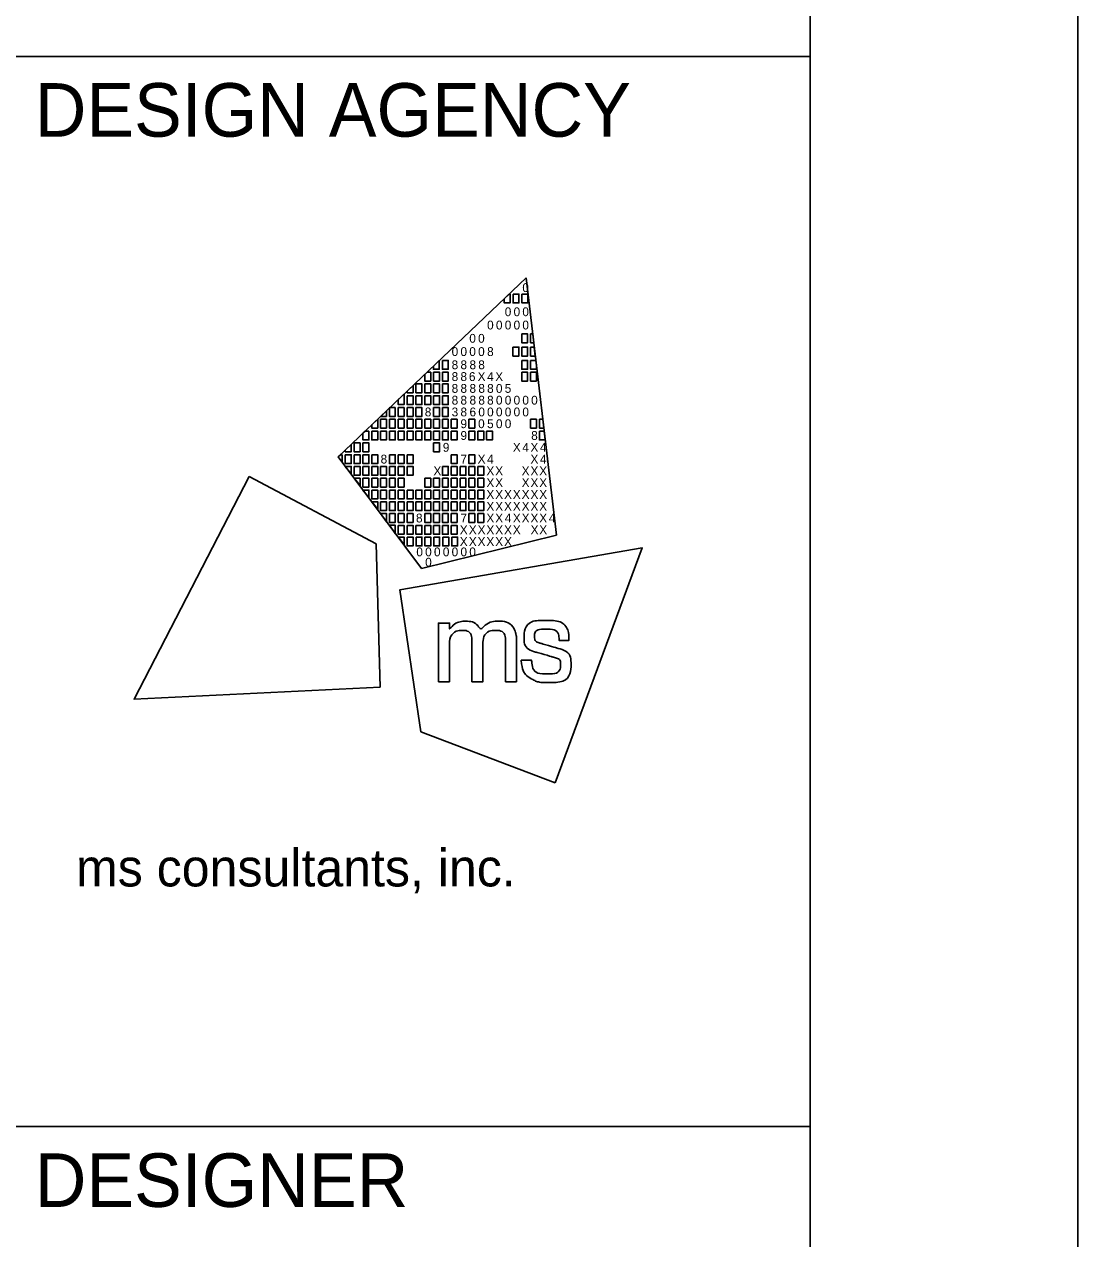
# Model space of a CAD drawing. Extents: x 0.1 to 34.1, y 0.1 to 22.1.
# Drawn here: x 32.106 to 34.076, y 2.39 to 4.659 of the extents above; entities that cross this region are included whole.
import ezdxf

# ---------------------------------------------------------------- set-up
doc = ezdxf.new("R2010")
doc.units = 0
for name, color, linetype in [('Default', 7, 'Continuous'), ('SH_Border', 7, 'Continuous'), ('SH_Cut_Line', 7, 'Continuous'), ('SH_Data', 7, 'Continuous')]:
    doc.layers.add(name, color=color, linetype=linetype)

msp = doc.modelspace()

# ---------------------------------------------------------------- linework, layer by layer
at = {"layer": 'Default'}
for p, q in [((32.6936, 3.8513), (33.0448, 4.1855)), ((33.0448, 4.1855), (33.0448, 4.1855)), ((33.0448, 4.1855), (33.1013, 3.7045)), ((32.849, 3.6424), (32.6936, 3.8513)), ((33.1013, 3.7045), (32.849, 3.6424))]:
    msp.add_line(p, q, dxfattribs=at)
for points in [[(33.0039, 4.1466), (33.0129, 4.1551), (33.0149, 4.1551), (33.0149, 4.1386), (33.0039, 4.1386)], [(33.0204, 4.1551), (33.0314, 4.1551), (33.0314, 4.1386), (33.0204, 4.1386)], [(33.0369, 4.1551), (33.0479, 4.1551), (33.0479, 4.1386), (33.0369, 4.1386)], [(33.0366, 4.0808), (33.0476, 4.0808), (33.0476, 4.0643), (33.0366, 4.0643)], [(33.0531, 4.0808), (33.0571, 4.0808), (33.059, 4.0643), (33.0531, 4.0643)], [(33.0201, 4.0561), (33.0312, 4.0561), (33.0312, 4.0395), (33.0201, 4.0395)], [(33.0366, 4.0561), (33.0476, 4.0561), (33.0476, 4.0395), (33.0366, 4.0395)], [(33.0531, 4.0561), (33.06, 4.0561), (33.0619, 4.0395), (33.0531, 4.0395)], [(32.8714, 4.0205), (32.8824, 4.0309), (32.8824, 4.0148), (32.8714, 4.0148)], [(32.8883, 4.0313), (32.8993, 4.0313), (32.8993, 4.0148), (32.8883, 4.0148)], [(33.0366, 4.0313), (33.0476, 4.0313), (33.0476, 4.0148), (33.0366, 4.0148)], [(33.0531, 4.0313), (33.0629, 4.0313), (33.0641, 4.0212), (33.0641, 4.0148), (33.0531, 4.0148)], [(32.8718, 4.0093), (32.8828, 4.0093), (32.8828, 3.9928), (32.8718, 3.9928)], [(32.8883, 4.0093), (32.8993, 4.0093), (32.8993, 3.9928), (32.8883, 3.9928)], [(33.0366, 4.0093), (33.0476, 4.0093), (33.0476, 3.9928), (33.0366, 3.9928)], [(33.0531, 4.0093), (33.0641, 4.0093), (33.0641, 3.9928), (33.0531, 3.9928)], [(32.8388, 3.9872), (32.8498, 3.9872), (32.8498, 3.9707), (32.8388, 3.9707)], [(32.8553, 3.9872), (32.8663, 3.9872), (32.8663, 3.9707), (32.8553, 3.9707)], [(32.8718, 3.9872), (32.8828, 3.9872), (32.8828, 3.9707), (32.8718, 3.9707)], [(32.8883, 3.9872), (32.8993, 3.9872), (32.8993, 3.9707), (32.8883, 3.9707)], [(32.8222, 3.9652), (32.8333, 3.9652), (32.8333, 3.9487), (32.8222, 3.9487)], [(32.8388, 3.9652), (32.8498, 3.9652), (32.8498, 3.9487), (32.8388, 3.9487)], [(32.8553, 3.9652), (32.8663, 3.9652), (32.8663, 3.9487), (32.8553, 3.9487)], [(32.8718, 3.9652), (32.8828, 3.9652), (32.8828, 3.9487), (32.8718, 3.9487)], [(32.8883, 3.9652), (32.8993, 3.9652), (32.8993, 3.9487), (32.8883, 3.9487)], [(32.8057, 3.9432), (32.8167, 3.9432), (32.8167, 3.9267), (32.8057, 3.9267)], [(32.8222, 3.9432), (32.8333, 3.9432), (32.8333, 3.9267), (32.8222, 3.9267)], [(32.8388, 3.9432), (32.8498, 3.9432), (32.8498, 3.9267), (32.8388, 3.9267)], [(32.8718, 3.9432), (32.8828, 3.9432), (32.8828, 3.9267), (32.8718, 3.9267)], [(32.8883, 3.9432), (32.8993, 3.9432), (32.8993, 3.9267), (32.8883, 3.9267)], [(32.7727, 3.9212), (32.7837, 3.9212), (32.7837, 3.9047), (32.7727, 3.9047)], [(32.7892, 3.9212), (32.8002, 3.9212), (32.8002, 3.9047), (32.7892, 3.9047)], [(32.8057, 3.9212), (32.8167, 3.9212), (32.8167, 3.9047), (32.8057, 3.9047)], [(32.8222, 3.9212), (32.8333, 3.9212), (32.8333, 3.9047), (32.8222, 3.9047)], [(32.8388, 3.9212), (32.8498, 3.9212), (32.8498, 3.9047), (32.8388, 3.9047)], [(32.8553, 3.9212), (32.8663, 3.9212), (32.8663, 3.9047), (32.8553, 3.9047)], [(32.8718, 3.9212), (32.8828, 3.9212), (32.8828, 3.9047), (32.8718, 3.9047)], [(32.8883, 3.9212), (32.8993, 3.9212), (32.8993, 3.9047), (32.8883, 3.9047)], [(32.9048, 3.9212), (32.9158, 3.9212), (32.9158, 3.9047), (32.9048, 3.9047)], [(32.9378, 3.9212), (32.9488, 3.9212), (32.9488, 3.9047), (32.9378, 3.9047)], [(33.0531, 3.9212), (33.0641, 3.9212), (33.0641, 3.9047), (33.0531, 3.9047)], [(33.0696, 3.9212), (33.0758, 3.9212), (33.0778, 3.9047), (33.0696, 3.9047)], [(32.7562, 3.8992), (32.7672, 3.8992), (32.7672, 3.8827), (32.7562, 3.8827)], [(32.7727, 3.8992), (32.7837, 3.8992), (32.7837, 3.8827), (32.7727, 3.8827)], [(32.7892, 3.8992), (32.8002, 3.8992), (32.8002, 3.8827), (32.7892, 3.8827)], [(32.8057, 3.8992), (32.8167, 3.8992), (32.8167, 3.8827), (32.8057, 3.8827)], [(32.8222, 3.8992), (32.8333, 3.8992), (32.8333, 3.8827), (32.8222, 3.8827)], [(32.8388, 3.8992), (32.8498, 3.8992), (32.8498, 3.8827), (32.8388, 3.8827)], [(32.8553, 3.8992), (32.8663, 3.8992), (32.8663, 3.8827), (32.8553, 3.8827)], [(32.8718, 3.8992), (32.8828, 3.8992), (32.8828, 3.8827), (32.8718, 3.8827)], [(32.8883, 3.8992), (32.8993, 3.8992), (32.8993, 3.8827), (32.8883, 3.8827)], [(32.9048, 3.8992), (32.9158, 3.8992), (32.9158, 3.8827), (32.9048, 3.8827)], [(32.9378, 3.8992), (32.9488, 3.8992), (32.9488, 3.8827), (32.9378, 3.8827)], [(32.9544, 3.8992), (32.9654, 3.8992), (32.9654, 3.8827), (32.9544, 3.8827)], [(32.9707, 3.8992), (32.9817, 3.8992), (32.9817, 3.8827), (32.9707, 3.8827)], [(33.0696, 3.8992), (33.0784, 3.8992), (33.0804, 3.8827), (33.0696, 3.8827)], [(32.7232, 3.8772), (32.7342, 3.8772), (32.7342, 3.8606), (32.7232, 3.8606)], [(32.7397, 3.8772), (32.7507, 3.8772), (32.7507, 3.8606), (32.7397, 3.8606)], [(32.8718, 3.8772), (32.8828, 3.8772), (32.8828, 3.8606), (32.8718, 3.8606)], [(32.7066, 3.8551), (32.7177, 3.8551), (32.7177, 3.8386), (32.7066, 3.8386)], [(32.7232, 3.8551), (32.7342, 3.8551), (32.7342, 3.8386), (32.7232, 3.8386)], [(32.7397, 3.8551), (32.7507, 3.8551), (32.7507, 3.8386), (32.7397, 3.8386)], [(32.7562, 3.8551), (32.7672, 3.8551), (32.7672, 3.8386), (32.7562, 3.8386)], [(32.7892, 3.8551), (32.8002, 3.8551), (32.8002, 3.8386), (32.7892, 3.8386)], [(32.8057, 3.8551), (32.8167, 3.8551), (32.8167, 3.8386), (32.8057, 3.8386)], [(32.8222, 3.8551), (32.8333, 3.8551), (32.8333, 3.8386), (32.8222, 3.8386)], [(32.9048, 3.8551), (32.9158, 3.8551), (32.9158, 3.8386), (32.9048, 3.8386)], [(32.9378, 3.8551), (32.9488, 3.8551), (32.9488, 3.8386), (32.9378, 3.8386)], [(32.7066, 3.8331), (32.7177, 3.8331), (32.7177, 3.8194)], [(32.7232, 3.8331), (32.7342, 3.8331), (32.7342, 3.8166), (32.7232, 3.8166)], [(32.7397, 3.8331), (32.7507, 3.8331), (32.7507, 3.8166), (32.7397, 3.8166)], [(32.7562, 3.8331), (32.7672, 3.8331), (32.7672, 3.8166), (32.7562, 3.8166)], [(32.7727, 3.8331), (32.7837, 3.8331), (32.7837, 3.8166), (32.7727, 3.8166)], [(32.7892, 3.8331), (32.8002, 3.8331), (32.8002, 3.8166), (32.7892, 3.8166)], [(32.8057, 3.8331), (32.8167, 3.8331), (32.8167, 3.8166), (32.8057, 3.8166)], [(32.8222, 3.8331), (32.8333, 3.8331), (32.8333, 3.8166), (32.8222, 3.8166)], [(32.8883, 3.8331), (32.8993, 3.8331), (32.8993, 3.8166), (32.8883, 3.8166)], [(32.9048, 3.8331), (32.9158, 3.8331), (32.9158, 3.8166), (32.9048, 3.8166)], [(32.9213, 3.8331), (32.9323, 3.8331), (32.9323, 3.8166), (32.9213, 3.8166)], [(32.9378, 3.8331), (32.9488, 3.8331), (32.9488, 3.8166), (32.9378, 3.8166)], [(32.9544, 3.8331), (32.9654, 3.8331), (32.9654, 3.8166), (32.9544, 3.8166)], [(32.7232, 3.8111), (32.7342, 3.8111), (32.7342, 3.7973)], [(32.7397, 3.8111), (32.7507, 3.8111), (32.7507, 3.7946), (32.7397, 3.7946)], [(32.7562, 3.8111), (32.7672, 3.8111), (32.7672, 3.7946), (32.7562, 3.7946)], [(32.7727, 3.8111), (32.7837, 3.8111), (32.7837, 3.7946), (32.7727, 3.7946)], [(32.7892, 3.8111), (32.8002, 3.8111), (32.8002, 3.7946), (32.7892, 3.7946)], [(32.8057, 3.8111), (32.8167, 3.8111), (32.8167, 3.7946), (32.8057, 3.7946)], [(32.8553, 3.8111), (32.8663, 3.8111), (32.8663, 3.7946), (32.8553, 3.7946)], [(32.8718, 3.8111), (32.8828, 3.8111), (32.8828, 3.7946), (32.8718, 3.7946)], [(32.8883, 3.8111), (32.8993, 3.8111), (32.8993, 3.7946), (32.8883, 3.7946)], [(32.9048, 3.8111), (32.9158, 3.8111), (32.9158, 3.7946), (32.9048, 3.7946)], [(32.9213, 3.8111), (32.9323, 3.8111), (32.9323, 3.7946), (32.9213, 3.7946)], [(32.9378, 3.8111), (32.9488, 3.8111), (32.9488, 3.7946), (32.9378, 3.7946)], [(32.9544, 3.8111), (32.9654, 3.8111), (32.9654, 3.7946), (32.9544, 3.7946)], [(32.7397, 3.7891), (32.7507, 3.7891), (32.7507, 3.7753)], [(32.7507, 3.7891), (32.7507, 3.7891), (32.7507, 3.7891)], [(32.7562, 3.7891), (32.7672, 3.7891), (32.7672, 3.7726), (32.7562, 3.7726)], [(32.7727, 3.7891), (32.7837, 3.7891), (32.7837, 3.7726), (32.7727, 3.7726)], [(32.7892, 3.7891), (32.8002, 3.7891), (32.8002, 3.7726), (32.7892, 3.7726)], [(32.8057, 3.7891), (32.8167, 3.7891), (32.8167, 3.7726), (32.8057, 3.7726)], [(32.8222, 3.7891), (32.8333, 3.7891), (32.8333, 3.7726), (32.8222, 3.7726)], [(32.8388, 3.7891), (32.8498, 3.7891), (32.8498, 3.7726), (32.8388, 3.7726)], [(32.8553, 3.7891), (32.8663, 3.7891), (32.8663, 3.7726), (32.8553, 3.7726)], [(32.8718, 3.7891), (32.8828, 3.7891), (32.8828, 3.7726), (32.8718, 3.7726)], [(32.8883, 3.7891), (32.8993, 3.7891), (32.8993, 3.7726), (32.8883, 3.7726)], [(32.9048, 3.7891), (32.9158, 3.7891), (32.9158, 3.7726), (32.9048, 3.7726)], [(32.9213, 3.7891), (32.9323, 3.7891), (32.9323, 3.7726), (32.9213, 3.7726)], [(32.9378, 3.7891), (32.9488, 3.7891), (32.9488, 3.7726), (32.9378, 3.7726)], [(32.9544, 3.7891), (32.9654, 3.7891), (32.9654, 3.7726), (32.9544, 3.7726)], [(32.7562, 3.7671), (32.7672, 3.7671), (32.7672, 3.7533)], [(32.7838, 3.7299), (32.7726, 3.7451), (32.7838, 3.7451)], [(32.7727, 3.7671), (32.7837, 3.7671), (32.7837, 3.7505), (32.7727, 3.7505)], [(32.7892, 3.7671), (32.8002, 3.7671), (32.8002, 3.7505), (32.7892, 3.7505)], [(32.7892, 3.745), (32.8002, 3.745), (32.8002, 3.7285), (32.7892, 3.7285)], [(32.8057, 3.7671), (32.8167, 3.7671), (32.8167, 3.7505), (32.8057, 3.7505)], [(32.8057, 3.745), (32.8167, 3.745), (32.8167, 3.7285), (32.8057, 3.7285)], [(32.8222, 3.7671), (32.8333, 3.7671), (32.8333, 3.7505), (32.8222, 3.7505)], [(32.8222, 3.745), (32.8333, 3.745), (32.8333, 3.7285), (32.8222, 3.7285)], [(32.8388, 3.7671), (32.8498, 3.7671), (32.8498, 3.7505), (32.8388, 3.7505)], [(32.8553, 3.7671), (32.8663, 3.7671), (32.8663, 3.7505), (32.8553, 3.7505)], [(32.8553, 3.745), (32.8663, 3.745), (32.8663, 3.7285), (32.8553, 3.7285)], [(32.8718, 3.7671), (32.8828, 3.7671), (32.8828, 3.7505), (32.8718, 3.7505)], [(32.8718, 3.745), (32.8828, 3.745), (32.8828, 3.7285), (32.8718, 3.7285)], [(32.8883, 3.7671), (32.8993, 3.7671), (32.8993, 3.7505), (32.8883, 3.7505)], [(32.8883, 3.745), (32.8993, 3.745), (32.8993, 3.7285), (32.8883, 3.7285)], [(32.9048, 3.7671), (32.9158, 3.7671), (32.9158, 3.7505), (32.9048, 3.7505)], [(32.9048, 3.745), (32.9158, 3.745), (32.9158, 3.7285), (32.9048, 3.7285)], [(32.9213, 3.7671), (32.9323, 3.7671), (32.9323, 3.7505), (32.9213, 3.7505)], [(32.9378, 3.7671), (32.9488, 3.7671), (32.9488, 3.7505), (32.9378, 3.7505)], [(32.9378, 3.745), (32.9488, 3.745), (32.9488, 3.7285), (32.9378, 3.7285)], [(32.9544, 3.7671), (32.9654, 3.7671), (32.9654, 3.7505), (32.9544, 3.7505)], [(32.9544, 3.745), (32.9654, 3.745), (32.9654, 3.7285), (32.9544, 3.7285)], [(32.8, 3.7076), (32.7892, 3.7231), (32.8002, 3.7231)], [(32.8057, 3.723), (32.8167, 3.723), (32.8167, 3.7065), (32.8057, 3.7065)], [(32.8222, 3.723), (32.8333, 3.723), (32.8333, 3.7065), (32.8222, 3.7065)], [(32.8388, 3.723), (32.8498, 3.723), (32.8498, 3.7065), (32.8388, 3.7065)], [(32.8553, 3.723), (32.8663, 3.723), (32.8663, 3.7065), (32.8553, 3.7065)], [(32.8718, 3.723), (32.8828, 3.723), (32.8828, 3.7065), (32.8718, 3.7065)], [(32.8883, 3.723), (32.8993, 3.723), (32.8993, 3.7065), (32.8883, 3.7065)], [(32.9048, 3.723), (32.9158, 3.723), (32.9158, 3.7065), (32.9048, 3.7065)], [(32.8062, 3.7011), (32.8167, 3.7011), (32.8168, 3.6869)], [(32.8223, 3.7011), (32.8333, 3.7011), (32.8333, 3.6846), (32.8223, 3.6846)], [(32.839, 3.7011), (32.85, 3.7011), (32.85, 3.6846), (32.839, 3.6846)], [(32.8554, 3.7011), (32.8664, 3.7011), (32.8664, 3.6846), (32.8554, 3.6846)], [(32.8721, 3.7011), (32.8831, 3.7011), (32.8831, 3.6846), (32.8721, 3.6846)], [(32.889, 3.701), (32.9, 3.701), (32.9, 3.6845), (32.889, 3.6845)], [(32.9056, 3.701), (32.9166, 3.701), (32.9166, 3.6845), (32.9056, 3.6845)]]:
    msp.add_lwpolyline(points, close=True, dxfattribs=at)
for points in [[(32.8663, 4.0093), (32.8596, 4.0093), (32.8553, 4.0052), (32.8553, 3.9928), (32.8663, 3.9928), (32.8663, 4.0093)], [(32.8333, 3.9842), (32.8222, 3.9737), (32.8222, 3.9707), (32.8333, 3.9707), (32.8333, 3.9842)], [(32.8167, 3.9685), (32.8057, 3.958), (32.8057, 3.9487), (32.8167, 3.9487), (32.8167, 3.9685)], [(32.7837, 3.9371), (32.7728, 3.9267), (32.7837, 3.9267), (32.7837, 3.9371)], [(32.8002, 3.9432), (32.7902, 3.9432), (32.7892, 3.9423), (32.7892, 3.9267), (32.8002, 3.9267), (32.8002, 3.9432)], [(32.7672, 3.9214), (32.7562, 3.9109), (32.7562, 3.9047), (32.7672, 3.9047), (32.7672, 3.9214)], [(32.7507, 3.8992), (32.7439, 3.8992), (32.7397, 3.8952), (32.7397, 3.8827), (32.7507, 3.8827), (32.7507, 3.8992)], [(32.7177, 3.8742), (32.7066, 3.8637), (32.7066, 3.8606), (32.7177, 3.8606), (32.7177, 3.8742)], [(32.7011, 3.8551), (32.6976, 3.8551), (32.6936, 3.8513), (32.7011, 3.8411), (32.7011, 3.8551)], [(32.5272, 3.8142), (32.3119, 3.3981), (32.7716, 3.4208), (32.7644, 3.6885), (32.5272, 3.8142)], [(33.0989, 3.2416), (33.2619, 3.6808), (32.8084, 3.6023), (32.8482, 3.3375), (33.0989, 3.2416)]]:
    msp.add_lwpolyline(points, dxfattribs=at)
for points in [[(32.8808, 3.4308), (32.8808, 3.4308), (32.8808, 3.5403), (32.8808, 3.5403), (32.8808, 3.5403), (32.9015, 3.5403), (32.9015, 3.5403), (32.9015, 3.5403), (32.9015, 3.5291), (32.9015, 3.5291), (32.9106, 3.5393), (32.9217, 3.5438), (32.9315, 3.5438), (32.9449, 3.5438), (32.9552, 3.5365), (32.9597, 3.526), (32.9675, 3.5374), (32.981, 3.544), (32.9926, 3.544), (33.0085, 3.544), (33.0211, 3.5344), (33.0254, 3.5206), (33.0254, 3.5206), (33.0254, 3.5205), (33.0254, 3.5205), (33.0261, 3.5183), (33.0267, 3.5166), (33.0267, 3.5064), (33.0267, 3.5064), (33.0267, 3.4308), (33.0267, 3.4308), (33.0267, 3.4308), (33.0063, 3.4308), (33.0063, 3.4308), (33.0063, 3.4308), (33.0063, 3.5041), (33.0063, 3.5041), (33.0063, 3.5195), (32.9979, 3.5268), (32.9871, 3.5268), (32.9755, 3.5268), (32.964, 3.5164), (32.964, 3.4995), (32.964, 3.4995), (32.964, 3.4308), (32.964, 3.4308), (32.964, 3.4308), (32.9434, 3.4308), (32.9434, 3.4308), (32.9434, 3.4308), (32.9434, 3.5053), (32.9434, 3.5053), (32.9434, 3.5197), (32.9348, 3.5268), (32.9257, 3.5268), (32.9144, 3.5268), (32.9014, 3.5164), (32.9014, 3.4956), (32.9014, 3.4956), (32.9014, 3.4308), (32.9014, 3.4308), (32.9014, 3.4308), (32.8808, 3.4308), (32.8808, 3.4308)], [(33.0356, 3.4702), (33.0356, 3.4702), (33.0355, 3.471), (33.0355, 3.471), (33.0355, 3.471), (33.0363, 3.471), (33.0363, 3.471), (33.0363, 3.471), (33.0543, 3.471), (33.0543, 3.471), (33.0543, 3.471), (33.0549, 3.471), (33.0549, 3.471), (33.0549, 3.471), (33.055, 3.4703), (33.055, 3.4703), (33.0563, 3.4548), (33.0647, 3.4454), (33.085, 3.4454), (33.1033, 3.4454), (33.1093, 3.4548), (33.1093, 3.4625), (33.1093, 3.4725), (33.1016, 3.4751), (33.0935, 3.4774), (33.0935, 3.4774), (33.063, 3.4861), (33.063, 3.4861), (33.0481, 3.4903), (33.0408, 3.5012), (33.0408, 3.5136), (33.0408, 3.5296), (33.0528, 3.5455), (33.0812, 3.5455), (33.1108, 3.5455), (33.1249, 3.5278), (33.1249, 3.5088), (33.1249, 3.5088), (33.1249, 3.5081), (33.1249, 3.5081), (33.1249, 3.5081), (33.1242, 3.5081), (33.1242, 3.5081), (33.1242, 3.5081), (33.1072, 3.5081), (33.1072, 3.5081), (33.1072, 3.5081), (33.1065, 3.5081), (33.1065, 3.5081), (33.1065, 3.5081), (33.1065, 3.5088), (33.1065, 3.5088), (33.1062, 3.5202), (33.0987, 3.5293), (33.0816, 3.5293), (33.0651, 3.5293), (33.0603, 3.5211), (33.0603, 3.5151), (33.0603, 3.5101), (33.0629, 3.5053), (33.0719, 3.5027), (33.0719, 3.5027), (33.1015, 3.4942), (33.1015, 3.4942), (33.1222, 3.4882), (33.1287, 3.4771), (33.1287, 3.4633), (33.1287, 3.4456), (33.117, 3.4292), (33.0847, 3.4292), (33.0712, 3.4292), (33.0637, 3.4314), (33.0583, 3.4342), (33.0451, 3.4408), (33.0369, 3.4529), (33.0356, 3.4702)]]:
    msp.add_open_spline(points, degree=3, dxfattribs=at)
at = {"layer": 'SH_Border'}
for p, q in [((32.076, 4.5994), (33.576, 4.5994)), ((32.076, 2.5994), (33.576, 2.5994))]:
    msp.add_line(p, q, dxfattribs=at)
msp.add_lwpolyline([(1.576, 21.5994), (33.576, 21.5994), (33.576, 0.5994), (1.576, 0.5994)], close=True, dxfattribs=at)
at = {"layer": 'SH_Cut_Line'}
msp.add_lwpolyline([(0.076, 0.0994), (34.076, 0.0994), (34.076, 22.0994), (0.076, 22.0994)], close=True, dxfattribs=at)
at = {"layer": 'SH_Data'}
msp.add_line((32.826, 3.5994), (32.826, 3.5994), dxfattribs=at)

# ---------------------------------------------------------------- texts
at = {"layer": 'Default'}
for s, p in [('0', (33.0377, 4.159)), ('0', (33.0048, 4.1139)), ('0', (33.0213, 4.1139)), ('0', (33.0377, 4.1139)), ('0', (32.9718, 4.0891)), ('0', (32.9883, 4.0891)), ('0', (33.0048, 4.0891)), ('0', (33.0213, 4.0891)), ('0', (33.0377, 4.0891)), ('0', (32.9385, 4.0643)), ('0', (32.955, 4.0643)), ('0', (32.9055, 4.0395)), ('0', (32.922, 4.0395)), ('0', (32.9385, 4.0395)), ('0', (32.955, 4.0395)), ('8', (32.9718, 4.0395)), ('8', (32.9055, 4.0148)), ('8', (32.922, 4.0148)), ('8', (32.9389, 4.0148)), ('8', (32.9553, 4.0148)), ('8', (32.9055, 3.9928)), ('8', (32.922, 3.9928)), ('6', (32.9378, 3.9928)), ('X', (32.9541, 3.9928)), ('4', (32.9718, 3.9928)), ('X', (32.987, 3.9928)), ('8', (32.9055, 3.9707)), ('8', (32.922, 3.9707)), ('8', (32.9389, 3.9707)), ('8', (32.9554, 3.9707)), ('8', (32.9718, 3.9707)), ('0', (32.9883, 3.9707)), ('5', (33.0047, 3.9707)), ('8', (32.9055, 3.9487)), ('8', (32.922, 3.9487)), ('8', (32.9389, 3.9487)), ('8', (32.9554, 3.9487)), ('8', (32.9718, 3.9487)), ('0', (32.9883, 3.9487)), ('0', (33.0048, 3.9487)), ('0', (33.0213, 3.9487)), ('0', (33.0377, 3.9487)), ('0', (33.0542, 3.9487)), ('8', (32.8553, 3.9267)), ('3', (32.9055, 3.9267)), ('8', (32.922, 3.9267)), ('6', (32.9389, 3.9267)), ('0', (32.9554, 3.9267)), ('0', (32.9718, 3.9267)), ('0', (32.9883, 3.9267)), ('0', (33.0048, 3.9267)), ('0', (33.0213, 3.9267)), ('0', (33.0377, 3.9267)), ('9', (32.922, 3.9047)), ('0', (32.955, 3.9047)), ('5', (32.9718, 3.9047)), ('0', (32.9883, 3.9047)), ('0', (33.0048, 3.9047)), ('9', (32.922, 3.8827)), ('8', (33.0542, 3.8827)), ('9', (32.889, 3.8606)), ('X', (33.0199, 3.8606)), ('4', (33.0377, 3.8606)), ('X', (33.0529, 3.8606)), ('4', (33.0706, 3.8606)), ('8', (32.7727, 3.8386)), ('7', (32.922, 3.8386)), ('X', (32.9541, 3.8386)), ('4', (32.9718, 3.8386)), ('X', (33.0529, 3.8386)), ('4', (33.0706, 3.8386)), ('X', (32.8715, 3.8166)), ('X', (32.9705, 3.8166)), ('X', (32.987, 3.8166)), ('X', (33.0364, 3.8166)), ('X', (33.0529, 3.8166)), ('X', (33.0693, 3.8166)), ('X', (32.9705, 3.7946)), ('X', (32.987, 3.7946)), ('X', (33.0364, 3.7946)), ('X', (33.0529, 3.7946)), ('X', (33.0693, 3.7946)), ('X', (32.9705, 3.7726)), ('X', (32.987, 3.7726)), ('X', (33.0035, 3.7726)), ('X', (33.0199, 3.7726)), ('X', (33.0364, 3.7726)), ('X', (33.0529, 3.7726)), ('X', (33.0693, 3.7726)), ('8', (32.8388, 3.7285)), ('7', (32.922, 3.7285)), ('X', (32.9705, 3.7505)), ('X', (32.9705, 3.7285)), ('X', (32.987, 3.7505)), ('X', (32.987, 3.7285)), ('X', (33.0035, 3.7505)), ('4', (33.0048, 3.7285)), ('X', (33.0199, 3.7505)), ('X', (33.0199, 3.7285)), ('X', (33.0364, 3.7505)), ('X', (33.0364, 3.7285)), ('X', (33.0529, 3.7505)), ('X', (33.0529, 3.7285)), ('X', (33.0693, 3.7505)), ('X', (33.0693, 3.7285)), ('4', (33.0871, 3.7285)), ('X', (32.9207, 3.7065)), ('X', (32.9376, 3.7065)), ('X', (32.954, 3.7065)), ('X', (32.9705, 3.7065)), ('X', (32.987, 3.7065)), ('X', (33.0035, 3.7065)), ('X', (33.0199, 3.7065)), ('X', (33.0532, 3.7065)), ('X', (33.0693, 3.7065)), ('X', (32.9207, 3.6845)), ('X', (32.9376, 3.6845)), ('X', (32.954, 3.6845)), ('X', (32.9705, 3.6845)), ('X', (32.987, 3.6845)), ('X', (33.0035, 3.6845)), ('0', (32.8395, 3.6652)), ('0', (32.856, 3.6652)), ('0', (32.8725, 3.6652)), ('0', (32.889, 3.6652)), ('0', (32.9055, 3.6652)), ('0', (32.922, 3.6652)), ('0', (32.9385, 3.6652)), ('0', (32.856, 3.646))]:
    msp.add_text(s, height=0.0165, rotation=360, dxfattribs=at).set_placement(p)
at = {"layer": 'SH_Border'}
msp.add_text('ms consultants, inc.', height=0.07, rotation=360, dxfattribs=at).set_placement((32.2033, 3.0483))
at = {"layer": 'SH_Data'}
for s, p in [('DESIGN AGENCY', (32.126, 4.4494)), ('DESIGNER', (32.126, 2.4494))]:
    msp.add_text(s, height=0.1, dxfattribs=at).set_placement(p)

doc.saveas('drawing.dxf')
